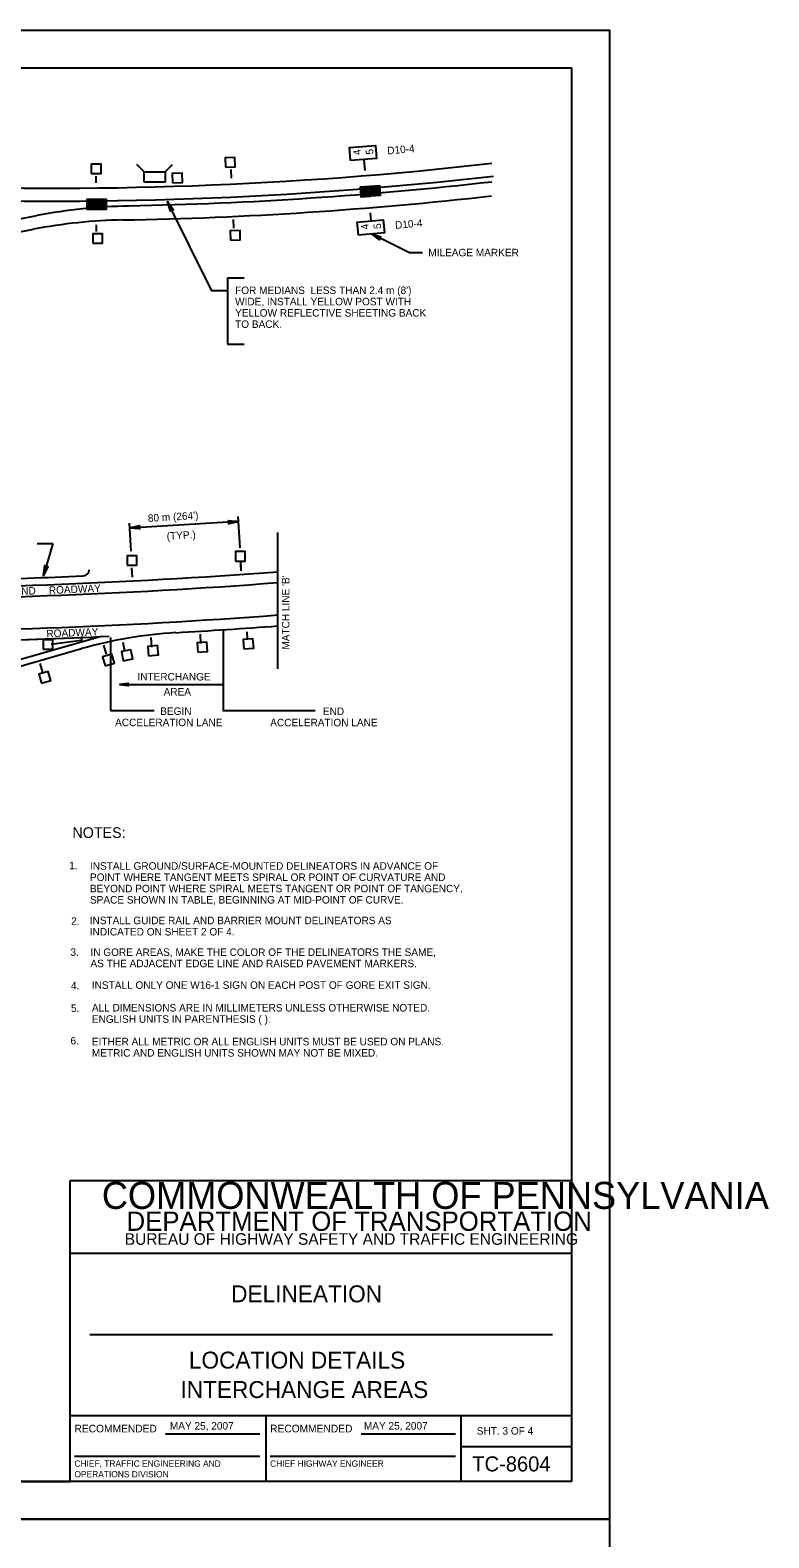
# Model space of a CAD drawing. Extents: x 640253 to 641999, y 298458 to 299646.
# Drawn here: x 641704 to 641999, y 299044 to 299646 of the extents above; entities that cross this region are included whole.
import ezdxf

# ---------------------------------------------------------------- set-up
doc = ezdxf.new("R2010")
doc.units = 0
for name, color, linetype in [('1', 7, 'Continuous'), ('2', 7, 'Continuous'), ('PLT-BNDY', 7, 'Continuous')]:
    doc.layers.add(name, color=color, linetype=linetype)

msp = doc.modelspace()

# ---------------------------------------------------------------- linework, layer by layer
at = {"layer": '1'}
for p, q in [((641134.31, 299630.63), (641920.31, 299630.63)), ((641920.31, 299066.63), (641920.31, 299630.63)), ((641720.31, 299066.63), (641720.31, 299186.63)), ((641720.31, 299186.63), (641920.31, 299186.63)), ((641920.31, 299157.63), (641720.31, 299157.63)), ((641728.06, 299125.31), (641912.56, 299125.31)), ((641720.31, 299093), (641920.31, 299093)), ((641798.31, 299093), (641798.31, 299066.63)), ((641876.19, 299066.63), (641876.19, 299093)), ((641758.24, 299085.57), (641795.87, 299085.57)), ((641836.24, 299085.57), (641873.87, 299085.57)), ((641876.19, 299080.63), (641920.31, 299080.63)), ((641721.99, 299076.68), (641795.87, 299076.68)), ((641799.99, 299076.68), (641873.87, 299076.68)), ((641920.31, 299066.63), (641134.31, 299066.63)), ((641134.31, 299066.63), (641720.31, 299066.63))]:
    msp.add_line(p, q, dxfattribs=at)
at = {"layer": '2'}
for p, q in [((641749.79, 299589.1), (641746.85, 299592.04)), ((641758.12, 299589.1), (641761.06, 299592.04)), ((641784.66, 299586.64), (641784.49, 299590.04)), ((641837.89, 299589.6), (641837.54, 299594.04)), ((641730.6, 299584.77), (641730.59, 299587.43)), ((641672.93, 299565.02), (641707.01, 299571.63)), ((641840.27, 299569.56), (641840.02, 299572.73)), ((641674.04, 299560.09), (641705.59, 299566.17)), ((641730.82, 299565.25), (641730.79, 299567.92)), ((641785.59, 299566.63), (641785.43, 299570.02)), ((641782.99, 299546.75), (641789.62, 299546.75)), ((641782.99, 299546.75), (641782.99, 299520.41)), ((641782.99, 299520.41), (641789.62, 299520.41)), ((641788.1, 299439.07), (641787.2, 299451.66)), ((641744.54, 299437.76), (641743.89, 299448.92)), ((641787.38, 299449.54), (641744, 299446.98)), ((641803.08, 299390.85), (641803.08, 299445.17)), ((641707.16, 299440.83), (641713.41, 299440.83)), ((641713.41, 299440.83), (641709.61, 299428.01)), ((641788.5, 299429.87), (641788.3, 299432.76)), ((641788.42, 299431.48), (641788.31, 299433.25)), ((641745.08, 299427.35), (641744.89, 299431.15)), ((641744.99, 299428.96), (641744.89, 299430.73)), ((641589.09, 299362.8), (641732.18, 299403.67)), ((641724.87, 299401.52), (641724.87, 299403.72)), ((641736.33, 299403.34), (641736.33, 299374.22)), ((641752.77, 299399.47), (641752.58, 299403.27)), ((641772.43, 299400.9), (641772.24, 299404.7)), ((641781.29, 299406.17), (641781.29, 299374.22)), ((641791.02, 299402.7), (641790.81, 299405.6)), ((641593.29, 299361.29), (641724.82, 299398.87)), ((641712.74, 299400.65), (641724.72, 299402.27)), ((641733.54, 299400.24), (641734.58, 299396.61)), ((641741.21, 299401.43), (641741.92, 299397.81)), ((641708.19, 299393), (641709.24, 299389.37)), ((641740.07, 299384.62), (641781.29, 299384.62)), ((641736.33, 299374.22), (641753.7, 299374.22)), ((641781.17, 299374.22), (641817.92, 299374.22))]:
    msp.add_line(p, q, dxfattribs=at)
for points in [[(641832.07, 299593.57), (641831.62, 299598.75), (641842, 299599.65), (641842.45, 299594.47)], [(641728.69, 299588.38), (641732.59, 299588.38), (641732.59, 299592.13), (641728.69, 299592.13)], [(641782.22, 299591), (641786.11, 299591.14), (641785.98, 299594.88), (641782.09, 299594.75)], [(641749.79, 299584.93), (641749.79, 299589.1), (641758.12, 299589.1), (641758.12, 299584.93)], [(641761.13, 299584.75), (641765.02, 299584.89), (641764.89, 299588.63), (641761, 299588.49)], [(641784.23, 299561.88), (641788.12, 299562.01), (641787.99, 299565.76), (641784.1, 299565.62)], [(641835.19, 299563.86), (641834.74, 299569.04), (641845.12, 299569.94), (641845.57, 299564.76)], [(641729.32, 299560.61), (641733.21, 299560.61), (641733.21, 299564.36), (641729.32, 299564.36)], [(641742.99, 299432.2), (641746.89, 299432.2), (641746.89, 299435.95), (641742.99, 299435.95)], [(641786.14, 299433.82), (641790.04, 299433.82), (641790.04, 299437.57), (641786.14, 299437.57)], [(641789.56, 299398.75), (641793.45, 299399.08), (641793.12, 299402.82), (641789.24, 299402.48)], [(641709.51, 299398.7), (641713.41, 299398.7), (641713.41, 299402.45), (641709.51, 299402.45)], [(641734.21, 299391.99), (641737.96, 299393.06), (641736.93, 299396.66), (641733.18, 299395.59)], [(641741.41, 299394), (641745.23, 299394.75), (641744.52, 299398.42), (641740.7, 299397.68)], [(641751.56, 299396.06), (641755.44, 299396.46), (641755.05, 299400.19), (641751.18, 299399.78)], [(641771.2, 299397.43), (641775.08, 299397.77), (641774.75, 299401.51), (641770.87, 299401.17)], [(641708.8, 299385.13), (641712.55, 299386.2), (641711.52, 299389.8), (641707.77, 299388.73)]]:
    msp.add_lwpolyline(points, close=True, dxfattribs=at)
for points in [[(641836.14, 299579.19), (641840.03, 299579.46), (641839.77, 299583.2), (641835.88, 299582.92), (641836.14, 299579.19), (641839.71, 299583.12), (641835.95, 299582.86), (641836.2, 299579.24), (641839.96, 299579.51), (641839.72, 299583.06), (641836.03, 299582.8), (641836.27, 299579.31), (641839.88, 299579.57), (641839.63, 299582.96), (641836.1, 299582.71), (641836.34, 299579.38), (641839.81, 299579.62), (641839.58, 299582.9), (641836.18, 299582.66), (641836.4, 299579.44), (641839.73, 299579.68), (641839.5, 299582.82), (641836.25, 299582.6), (641836.46, 299579.5), (641839.66, 299579.75), (641839.42, 299582.74), (641836.33, 299582.53), (641836.52, 299579.57), (641839.58, 299579.81), (641839.36, 299582.67), (641836.4, 299582.46), (641836.57, 299579.66), (641839.49, 299579.89), (641839.3, 299582.58), (641836.49, 299582.39), (641836.64, 299579.71), (641839.38, 299579.95), (641839.22, 299582.51), (641836.57, 299582.33), (641836.71, 299579.78), (641839.3, 299580.01), (641839.13, 299582.45), (641836.66, 299582.25), (641836.79, 299579.83), (641839.21, 299580.07), (641839.04, 299582.36), (641836.75, 299582.17), (641836.78, 299581.07), (641836.86, 299579.91), (641839.13, 299580.14), (641838.95, 299582.26), (641836.84, 299582.07), (641836.94, 299579.99), (641839.04, 299580.2), (641838.87, 299582.17), (641836.95, 299581.98), (641837.04, 299580.08), (641838.91, 299580.26), (641838.76, 299582.04), (641837.09, 299581.88), (641837.15, 299580.22), (641838.75, 299580.36), (641838.62, 299581.92), (641837.26, 299581.77), (641837.28, 299580.34), (641837.29, 299580.34), (641838.6, 299580.49), (641838.5, 299581.77), (641837.4, 299581.65), (641837.42, 299580.48), (641838.43, 299580.61), (641838.37, 299581.6), (641837.55, 299581.53), (641837.57, 299580.65), (641838.27, 299580.73), (641838.19, 299581.46), (641837.72, 299581.4), (641837.75, 299580.8), (641838.08, 299580.85), (641838.05, 299581.3), (641837.91, 299581.31), (641837.91, 299580.95)], [(641840.07, 299579.5), (641843.97, 299579.77), (641843.7, 299583.51), (641839.81, 299583.24), (641840.07, 299579.5), (641843.64, 299583.44), (641839.88, 299583.17), (641840.14, 299579.56), (641843.9, 299579.82), (641843.65, 299583.37), (641839.97, 299583.11), (641840.21, 299579.63), (641843.82, 299579.89), (641843.57, 299583.28), (641840.04, 299583.03), (641840.27, 299579.7), (641843.74, 299579.94), (641843.52, 299583.21), (641840.11, 299582.98), (641840.34, 299579.76), (641843.66, 299580), (641843.43, 299583.14), (641840.18, 299582.91), (641840.39, 299579.82), (641843.59, 299580.06), (641843.36, 299583.06), (641840.26, 299582.84), (641840.45, 299579.89), (641843.52, 299580.13), (641843.3, 299582.99), (641840.33, 299582.78), (641840.51, 299579.97), (641843.42, 299580.2), (641843.23, 299582.89), (641840.43, 299582.71), (641840.57, 299580.03), (641843.32, 299580.27), (641843.15, 299582.83), (641840.51, 299582.64), (641840.64, 299580.1), (641843.24, 299580.32), (641843.07, 299582.76), (641840.59, 299582.57), (641840.72, 299580.15), (641843.14, 299580.39), (641842.98, 299582.68), (641840.68, 299582.49), (641840.71, 299581.39), (641840.79, 299580.22), (641843.06, 299580.46), (641842.88, 299582.57), (641840.77, 299582.39), (641840.87, 299580.3), (641842.97, 299580.52), (641842.8, 299582.49), (641840.88, 299582.3), (641840.98, 299580.4), (641842.84, 299580.58), (641842.7, 299582.35), (641841.03, 299582.2), (641841.08, 299580.53), (641842.69, 299580.67), (641842.56, 299582.24), (641841.19, 299582.09), (641841.21, 299580.66), (641841.22, 299580.66), (641842.53, 299580.8), (641842.43, 299582.08), (641841.33, 299581.97), (641841.35, 299580.8), (641842.37, 299580.93), (641842.31, 299581.92), (641841.48, 299581.84), (641841.5, 299580.96), (641842.2, 299581.04), (641842.12, 299581.78), (641841.66, 299581.72), (641841.68, 299581.11), (641842.02, 299581.17), (641841.99, 299581.61), (641841.84, 299581.63), (641841.84, 299581.27)], [(641726.93, 299574.27), (641730.83, 299574.27), (641730.83, 299578.01), (641726.93, 299578.01), (641726.93, 299574.27), (641730.77, 299577.94), (641727, 299577.94), (641727, 299574.32), (641730.77, 299574.32), (641730.77, 299577.88), (641727.07, 299577.88), (641727.07, 299574.39), (641730.69, 299574.39), (641730.68, 299577.79), (641727.14, 299577.79), (641727.14, 299574.44), (641730.62, 299574.44), (641730.62, 299577.73), (641727.21, 299577.73), (641727.21, 299574.5), (641730.54, 299574.51), (641730.53, 299577.66), (641727.28, 299577.66), (641727.27, 299574.56), (641730.48, 299574.58), (641730.46, 299577.59), (641727.35, 299577.59), (641727.34, 299574.63), (641730.41, 299574.65), (641730.39, 299577.52), (641727.42, 299577.52), (641727.4, 299574.71), (641730.32, 299574.73), (641730.32, 299577.42), (641727.51, 299577.44), (641727.47, 299574.75), (641730.22, 299574.8), (641730.23, 299577.37), (641727.58, 299577.37), (641727.54, 299574.82), (641730.14, 299574.86), (641730.14, 299577.31), (641727.66, 299577.29), (641727.62, 299574.86), (641730.06, 299574.93), (641730.05, 299577.23), (641727.75, 299577.2), (641727.7, 299576.1), (641727.7, 299574.93), (641729.98, 299575.01), (641729.95, 299577.13), (641727.83, 299577.1), (641727.79, 299575.01), (641729.89, 299575.08), (641729.86, 299577.06), (641727.93, 299577), (641727.89, 299575.1), (641729.76, 299575.14), (641729.75, 299576.93), (641728.07, 299576.89), (641728.01, 299575.22), (641729.62, 299575.25), (641729.6, 299576.82), (641728.22, 299576.76), (641728.15, 299575.34), (641728.16, 299575.34), (641729.47, 299575.39), (641729.46, 299576.67), (641728.36, 299576.64), (641728.29, 299575.47), (641729.32, 299575.53), (641729.32, 299576.52), (641728.5, 299576.5), (641728.46, 299575.62), (641729.16, 299575.65), (641729.13, 299576.39), (641728.67, 299576.36), (641728.64, 299575.76), (641728.99, 299575.79), (641728.99, 299576.24), (641728.84, 299576.27), (641728.82, 299575.91)], [(641730.87, 299574.27), (641734.77, 299574.27), (641734.77, 299578.01), (641730.87, 299578.01), (641730.87, 299574.27), (641734.7, 299577.94), (641730.93, 299577.94), (641730.93, 299574.32), (641734.7, 299574.32), (641734.7, 299577.88), (641731.01, 299577.88), (641731.01, 299574.39), (641734.62, 299574.39), (641734.62, 299577.79), (641731.08, 299577.79), (641731.08, 299574.44), (641734.56, 299574.44), (641734.56, 299577.73), (641731.15, 299577.73), (641731.15, 299574.5), (641734.48, 299574.51), (641734.47, 299577.66), (641731.21, 299577.66), (641731.2, 299574.56), (641734.41, 299574.58), (641734.39, 299577.59), (641731.28, 299577.59), (641731.27, 299574.63), (641734.34, 299574.65), (641734.32, 299577.52), (641731.35, 299577.52), (641731.33, 299574.71), (641734.26, 299574.73), (641734.26, 299577.42), (641731.44, 299577.44), (641731.4, 299574.75), (641734.16, 299574.81), (641734.17, 299577.37), (641731.52, 299577.37), (641731.48, 299574.82), (641734.08, 299574.86), (641734.08, 299577.31), (641731.59, 299577.29), (641731.56, 299574.86), (641733.99, 299574.93), (641733.98, 299577.23), (641731.68, 299577.2), (641731.63, 299576.1), (641731.63, 299574.93), (641733.91, 299575.01), (641733.88, 299577.14), (641731.76, 299577.1), (641731.72, 299575.01), (641733.83, 299575.08), (641733.8, 299577.06), (641731.87, 299577), (641731.83, 299575.1), (641733.7, 299575.14), (641733.68, 299576.93), (641732, 299576.89), (641731.95, 299575.22), (641733.55, 299575.25), (641733.53, 299576.82), (641732.16, 299576.76), (641732.08, 299575.34), (641732.09, 299575.34), (641733.41, 299575.39), (641733.4, 299576.68), (641732.29, 299576.64), (641732.23, 299575.47), (641733.25, 299575.53), (641733.26, 299576.52), (641732.43, 299576.5), (641732.39, 299575.62), (641733.09, 299575.65), (641733.07, 299576.39), (641732.6, 299576.36), (641732.58, 299575.76), (641732.92, 299575.79), (641732.92, 299576.24), (641732.77, 299576.27), (641732.75, 299575.91)], [(641782.99, 299541.63), (641776.74, 299541.63), (641759.14, 299577.21)], [(641760.39, 299573.6), (641760.58, 299573.85), (641759.14, 299577.21), (641760.39, 299573.6), (641760.33, 299573.35), (641759.14, 299577.21), (641760.91, 299574.02), (641761.22, 299574.02), (641759.14, 299577.21), (641761.47, 299573.92), (641761.22, 299574.02)], [(641860.81, 299556.75), (641855.6, 299556.75), (641840.38, 299564.31)], [(641843.57, 299562.22), (641843.54, 299562.52), (641840.38, 299564.31), (641843.57, 299562.22), (641843.65, 299561.99), (641840.38, 299564.31), (641843.72, 299562.86), (641843.96, 299563.05), (641840.38, 299564.31), (641844.21, 299563.12), (641843.96, 299563.05)], [(641747.81, 299446.87), (641747.65, 299447.14), (641744, 299447.12), (641747.81, 299446.87), (641748.01, 299446.72), (641744, 299447.12), (641747.62, 299447.52), (641747.74, 299447.8), (641744, 299447.12), (641747.93, 299447.99), (641747.74, 299447.8)], [(641783.57, 299449.79), (641783.73, 299449.52), (641787.38, 299449.54), (641783.57, 299449.79), (641783.37, 299449.94), (641787.38, 299449.54), (641783.75, 299449.14), (641783.64, 299448.87), (641787.38, 299449.54), (641783.44, 299448.67), (641783.64, 299448.87)], [(641711.14, 299431.51), (641710.84, 299431.45), (641709.61, 299428.01), (641711.14, 299431.51), (641711.35, 299431.65), (641709.61, 299428.01), (641710.47, 299431.56), (641710.25, 299431.76), (641709.61, 299428.01), (641710.13, 299432.01), (641710.25, 299431.76)], [(641743.22, 299384.23), (641743.1, 299384.45), (641740.07, 299384.62), (641743.22, 299384.23), (641743.38, 299384.09), (641740.07, 299384.62), (641743.1, 299384.78), (641743.21, 299385.01), (641740.07, 299384.62), (641743.38, 299385.15), (641743.21, 299385.01)]]:
    msp.add_lwpolyline(points, dxfattribs=at)
for centre, radius, start, end in [((641713.53, 301122.08), 1539.51, 267.61256, 276.52429), ((641713.53, 301122.08), 1544.66, 267.61256, 276.52429), ((641713.53, 301122.08), 1546.82, 271.11716, 276.48929), ((641713.53, 301122.08), 1552.43, 271.024, 276.46547), ((641747.52, 299361.36), 214.14, 91.02364, 100.90658), ((641745, 299361.65), 208.29, 91.02364, 100.90658), ((641618.76, 301866.5), 2443.88, 270.0023, 274.32557), ((641617.17, 301869.36), 2443.88, 271.50321, 272.53479), ((641725.38, 299430.4), 2.53, 267.21992, 357.13947), ((641618.76, 301866.5), 2448.22, 270.0023, 274.31789), ((641618.76, 301866.5), 2461.1, 270.0023, 274.29526), ((641618.76, 301866.5), 2465.44, 270.0023, 272.72047), ((641618.76, 301866.5), 2465.43, 270.0023, 272.63682), ((641772.51, 299231.98), 173.57, 93.34006, 105.94714), ((641618.76, 301866.5), 2465.44, 273.34006, 274.28767)]:
    msp.add_arc(centre, radius, start, end, dxfattribs=at)
at = {"layer": 'PLT-BNDY'}
for points in [[(641094.31, 299645.63), (641935.31, 299645.63), (641935.31, 299051.63), (641094.31, 299051.63)], [(641094.31, 299051.63), (641935.31, 299051.63), (641935.31, 298457.63), (641094.31, 298457.63)]]:
    msp.add_lwpolyline(points, close=True, dxfattribs=at)

# ---------------------------------------------------------------- texts
at = {"layer": '1'}
for s, height, p in [('COMMONWEALTH OF PENNSYLVANIA', 10.7828, (641732.9, 299175.36)), ('DEPARTMENT OF TRANSPORTATION', 7.6837, (641742.76, 299166.61)), ('BUREAU OF HIGHWAY SAFETY AND TRAFFIC ENGINEERING', 4.6253, (641742.04, 299161.04)), ('DELINEATION', 6.75, (641784.46, 299138.1)), ('LOCATION DETAILS', 6.75, (641767.61, 299111.66)), ('INTERCHANGE AREAS', 6.75, (641764.24, 299099.91)), ('RECOMMENDED', 3.048, (641721.99, 299086.2)), ('RECOMMENDED', 3.048, (641799.99, 299086.2)), ('SHT. 3 OF 4', 3, (641882.4, 299085.31)), ('CHIEF, TRAFFIC ENGINEERING AND', 2.5, (641721.99, 299072.51)), ('CHIEF HIGHWAY ENGINEER', 2.5, (641799.99, 299072.51)), ('TC-8604', 6, (641880.6, 299070.63)), ('OPERATIONS DIVISION', 2.5, (641721.99, 299068.26))]:
    msp.add_text(s, height=height, dxfattribs=at).set_placement(p)
at = {"layer": '2'}
for s, rotation, p in [('4', 99.90169, (641836.32, 299596.04)), ('5', 94.93018, (641841.23, 299596.14)), ('D10-4', 4.92854, (641846.83, 299596.04)), ('4', 99.90169, (641839.43, 299566.33)), ('5', 94.93018, (641844.34, 299566.43)), ('D10-4', 4.92854, (641849.94, 299566.33)), ("80 m (264')", 3.36646, (641751.35, 299449.41)), ('(TYP.)', 3.36646, (641758.84, 299442.26)), ("MATCH LINE 'B'", 90, (641807.7, 299398.49)), ('WESTBOUND', 1.74068, (641680.51, 299419.69)), ('ROADWAY', 2.36512, (641711.82, 299420.65)), ('ROADWAY', 2.36512, (641710.85, 299403.33))]:
    msp.add_text(s, height=3, rotation=rotation, dxfattribs=at).set_placement(p)
for s, height, p in [('MILEAGE MARKER', 3, (641863.08, 299555.4)), ("FOR MEDIANS  LESS THAN 2.4 m (8') ", 3, (641786.03, 299540.34)), ('WIDE, INSTALL YELLOW POST WITH ', 3, (641786.03, 299535.84)), ('YELLOW REFLECTIVE SHEETING BACK ', 3, (641786.03, 299531.34)), ('TO BACK.', 3, (641786.03, 299526.84)), ('INTERCHANGE', 3, (641747.09, 299386.17)), ('AREA', 3, (641757.53, 299380.17)), ('BEGIN', 3, (641756.18, 299372.44)), ('END', 3, (641821.04, 299372.39)), ('ACCELERATION LANE', 3, (641738.19, 299367.94)), ('ACCELERATION LANE', 3, (641800.05, 299367.89)), ('NOTES:', 4.25, (641721.19, 299323.37)), ('1. ', 3, (641719.85, 299310.86)), ('INSTALL GROUND/SURFACE-MOUNTED DELINEATORS IN ADVANCE OF', 3, (641728.16, 299310.68)), ('POINT WHERE TANGENT MEETS SPIRAL OR POINT OF CURVATURE AND', 3, (641728.16, 299306.18)), ('BEYOND POINT WHERE SPIRAL MEETS TANGENT OR POINT OF TANGENCY.', 3, (641728.16, 299301.68)), ('SPACE SHOWN IN TABLE, BEGINNING AT MID-POINT OF CURVE.', 3, (641728.16, 299297.18)), ('2. ', 3, (641720.67, 299288.7)), ('INSTALL GUIDE RAIL AND BARRIER MOUNT DELINEATORS AS', 3, (641728.08, 299288.94)), ('INDICATED ON SHEET 2 OF 4.', 3, (641728.08, 299284.44)), ('3. ', 3, (641720.4, 299276.32)), ('IN GORE AREAS, MAKE THE COLOR OF THE DELINEATORS THE SAME,', 3, (641728.36, 299276.28)), ('AS THE ADJACENT EDGE LINE AND RAISED PAVEMENT MARKERS.', 3, (641728.36, 299271.78)), ('4. ', 3, (641720.59, 299262.97)), ('INSTALL ONLY ONE W16-1 SIGN ON EACH POST OF GORE EXIT SIGN.', 3, (641728.92, 299263.16)), ('5. ', 3, (641720.59, 299253.93)), ('ALL DIMENSIONS ARE IN MILLIMETERS UNLESS OTHERWISE NOTED.  ', 3, (641728.92, 299254.11)), ('ENGLISH UNITS IN PARENTHESIS ( ).', 3, (641728.92, 299249.61)), ('6. ', 3, (641720.4, 299240.98)), ('EITHER ALL METRIC OR ALL ENGLISH UNITS MUST BE USED ON PLANS.  ', 3, (641728.92, 299240.61)), ('METRIC AND ENGLISH UNITS SHOWN MAY NOT BE MIXED.', 3, (641728.92, 299236.11)), ('MAY 25, 2007', 3, (641760.03, 299087.31)), ('MAY 25, 2007', 3, (641837.39, 299087.31))]:
    msp.add_text(s, height=height, dxfattribs=at).set_placement(p)

doc.saveas('drawing.dxf')
